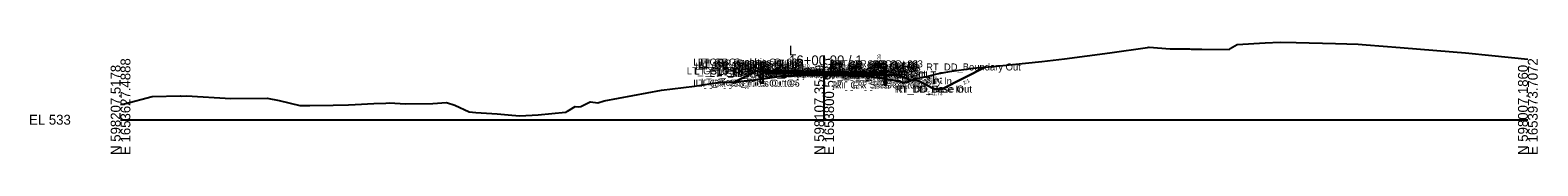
# Model space of a CAD drawing. Extents: x -26 to 403, y -10 to 6021.
# Drawn here: x -25.7 to 402.8, y 4490.3 to 4522.1 of the extents above; entities that cross this region are included whole.
import ezdxf

# ---------------------------------------------------------------- set-up
doc = ezdxf.new("R2010")
doc.units = 0
for name, color, linetype in [('Default', 7, 'Continuous'), ('Exist Cross Section Cell', 7, 'Continuous'), ('Exist XS Ground Line', 7, 'Continuous'), ('Prop CMT Conc Surface', 7, 'Continuous'), ('Prop CMT Concrete Structures', 7, 'Continuous'), ('Prop CMT Ditch DDE', 7, 'Continuous'), ('Prop CMT Guardrail Graphics', 7, 'Continuous'), ('Prop CMT Guardrail SBG', 7, 'Continuous'), ('Prop CMT Pvmt Course 1', 7, 'Continuous'), ('Prop CMT Pvmt Course 2', 7, 'Continuous'), ('Prop CMT Pvmt Course 3', 7, 'Continuous'), ('Prop CMT Pvmt Course SBG', 7, 'Continuous'), ('Prop CMT Pvmt Surface', 7, 'Continuous'), ('Prop CMT Pvmt Surface Shoulder', 7, 'Continuous'), ('Prop CMT Shld Paved Course 1', 7, 'Continuous'), ('Prop CMT Shld Paved Course 2', 7, 'Continuous'), ('Prop CMT Shld Paved Course 3', 7, 'Continuous'), ('Prop CMT Slope Grass', 7, 'Continuous'), ('Prop CMT Subgrade Earthwork', 7, 'Continuous'), ('Prop XS Ditch Slope Text', 7, 'Continuous'), ('Prop XS Ditch Standard Text', 7, 'Continuous'), ('Prop XS Earthwork Shape', 7, 'Continuous'), ('Prop XS Hydro Elevations', 7, 'Continuous'), ('Prop XS SE Text', 7, 'Continuous'), ('Prop XS Side Slope Text', 7, 'Continuous')]:
    doc.layers.add(name, color=color, linetype=linetype)

msp = doc.modelspace()

# ---------------------------------------------------------------- linework, layer by layer
at = {"layer": 'Exist Cross Section Cell'}
for p, q in [((200, 4500), (200, 4518.29)), ((0, 4500), (200, 4500)), ((200, 4500), (400, 4500))]:
    msp.add_line(p, q, dxfattribs=at)
at = {"layer": 'Exist XS Ground Line'}
msp.add_lwpolyline([(0, 4504.47), (1.1, 4504.47), (1.14, 4504.49), (8.98, 4506.58), (17.02, 4506.83), (17.45, 4506.69), (18.72, 4506.8), (31.36, 4506), (41.72, 4506.1), (45.04, 4505.46), (51, 4504.08), (52.98, 4504.02), (53.82, 4504.08), (60.4, 4504.18), (64.75, 4504.27), (66.64, 4504.35), (71.98, 4504.58), (75.42, 4504.73), (76.51, 4504.81), (80.85, 4504.51), (88.73, 4504.62), (92.69, 4504.94), (95.02, 4504.15), (99.13, 4502.25), (101.02, 4502.08), (107.07, 4501.64), (111.26, 4501.34), (113.49, 4501.1), (118.67, 4501.38), (126.43, 4502.17), (126.68, 4502.19), (127.05, 4502.43), (129.22, 4503.79), (130.08, 4503.69), (130.85, 4503.8), (133.14, 4504.95), (133.5, 4505.11), (133.55, 4505.12), (135.69, 4504.83), (137.48, 4505.4), (153.76, 4508.44), (163.12, 4509.52), (170.36, 4510.67), (174.48, 4510.7), (179.92, 4511.23), (187.84, 4512.43), (194.8, 4512.56), (199.74, 4512.67), (200, 4512.66), (209.87, 4512.51), (211.57, 4512.48), (213.96, 4512.08), (220.01, 4511.12), (221.77, 4510.76), (222.74, 4510.5), (223.04, 4510.58), (223.94, 4510.79), (225.2, 4511.36), (225.55, 4511.55), (226.64, 4511.82), (228.27, 4512.07), (229.14, 4512.3), (231.64, 4512.98), (235.64, 4513.72), (242.35, 4514.7), (249.87, 4515.35), (261.9, 4516.52), (268.33, 4517.32), (281.23, 4519.06), (291.85, 4520.55), (292.28, 4520.61), (292.35, 4520.6), (298.31, 4520.12), (303.85, 4520.11), (304.34, 4520.1), (307.32, 4520.07), (315.13, 4519.98), (315.43, 4520.23), (317.39, 4521.36), (325.38, 4521.82), (329.59, 4522.06), (334.12, 4521.98), (345.34, 4521.66), (351.76, 4521.49), (354.05, 4521.33), (363.7, 4520.53), (378.73, 4519.29), (382.28, 4518.98), (389.75, 4518.28), (400, 4517.19)], dxfattribs=at)
at = {"layer": 'Prop CMT Conc Surface'}
msp.add_lwpolyline([(213.81, 4513.48), (216.15, 4513.39), (216.81, 4513.73)], dxfattribs=at)
at = {"layer": 'Prop CMT Concrete Structures'}
for points in [[(213.81, 4513.48), (216.15, 4513.39), (216.81, 4513.73)], [(213.81, 4513.06), (213.81, 4513.48)], [(216.81, 4513.06), (213.81, 4513.06)], [(216.81, 4513.73), (216.81, 4513.06)]]:
    msp.add_lwpolyline(points, dxfattribs=at)
at = {"layer": 'Prop CMT Ditch DDE'}
msp.add_lwpolyline([(224.81, 4511.19), (226.81, 4511.02), (231.39, 4508.73), (233.39, 4508.73), (245.96, 4515.01)], dxfattribs=at)
at = {"layer": 'Prop CMT Guardrail Graphics'}
for points in [[(181.9, 4510.39), (181.9, 4516.39)], [(181.9, 4516.39), (183.23, 4516.39), (183.5, 4516.1)], [(183.5, 4515.52), (183.23, 4515.22), (182.57, 4515.22)], [(182.57, 4515.22), (182.57, 4510.39)], [(183.5, 4516.1), (183.23, 4515.81)], [(183.23, 4515.81), (183.5, 4515.52)], [(182.57, 4510.39), (181.9, 4510.39)]]:
    msp.add_lwpolyline(points, dxfattribs=at)
at = {"layer": 'Prop CMT Guardrail SBG'}
for points in [[(217.75, 4515.89), (216.42, 4515.89), (216.15, 4515.59)], [(216.15, 4515.59), (216.42, 4515.3)], [(216.42, 4515.3), (216.15, 4515.01)], [(216.15, 4515.01), (216.42, 4514.72), (217.08, 4514.72)], [(217.08, 4514.72), (217.08, 4509.89)], [(217.75, 4509.89), (217.75, 4515.89)], [(217.08, 4509.89), (217.75, 4509.89)]]:
    msp.add_lwpolyline(points, dxfattribs=at)
at = {"layer": 'Prop CMT Pvmt Course 1'}
for points in [[(200, 4513.76), (188, 4513.88)], [(188, 4513.88), (188, 4513.67)], [(188, 4513.67), (200, 4513.55)], [(200, 4513.55), (200, 4513.76)], [(200, 4513.76), (212, 4513.52)], [(200, 4513.55), (200, 4513.76)], [(212, 4513.31), (200, 4513.55)], [(212, 4513.52), (212, 4513.31)]]:
    msp.add_lwpolyline(points, dxfattribs=at)
msp.add_lwpolyline([(200, 4513.55), (200, 4513.55), (200, 4513.55), (200, 4513.55)], close=True, dxfattribs=at)
msp.add_lwpolyline([(200, 4513.55), (200, 4513.55), (200, 4513.55), (200, 4513.55)], close=True, dxfattribs=at)
at = {"layer": 'Prop CMT Pvmt Course 2'}
for points in [[(200, 4513.55), (188, 4513.67)], [(188, 4513.67), (188, 4513.46)], [(188, 4513.46), (200, 4513.34)], [(200, 4513.34), (200, 4513.55)], [(200, 4513.34), (200, 4513.55)], [(200, 4513.55), (212, 4513.31)], [(212, 4513.1), (200, 4513.34)], [(212, 4513.31), (212, 4513.1)]]:
    msp.add_lwpolyline(points, dxfattribs=at)
at = {"layer": 'Prop CMT Pvmt Course 3'}
for points in [[(200, 4513.34), (188, 4513.46)], [(188, 4513.46), (188, 4513.13)], [(188, 4513.13), (200, 4513.01)], [(200, 4513.01), (200, 4513.34)], [(200, 4513.34), (212, 4513.1)], [(200, 4513.01), (200, 4513.34)], [(212, 4512.77), (200, 4513.01)], [(212, 4513.1), (212, 4512.77)]]:
    msp.add_lwpolyline(points, dxfattribs=at)
at = {"layer": 'Prop CMT Pvmt Course SBG'}
for points in [[(213.81, 4513.06), (216.81, 4513.06), (217.31, 4513.06), (217.65, 4512.73)], [(213.81, 4512.73), (213.81, 4513.06)], [(217.65, 4512.73), (213.81, 4512.73)]]:
    msp.add_lwpolyline(points, dxfattribs=at)
at = {"layer": 'Prop CMT Pvmt Surface'}
for points in [[(200, 4513.76), (188, 4513.88)], [(200, 4513.76), (212, 4513.52)]]:
    msp.add_lwpolyline(points, dxfattribs=at)
at = {"layer": 'Prop CMT Pvmt Surface Shoulder'}
for points in [[(188, 4513.88), (184, 4513.92)], [(212, 4513.52), (213.81, 4513.48)]]:
    msp.add_lwpolyline(points, dxfattribs=at)
at = {"layer": 'Prop CMT Shld Paved Course 1'}
for points in [[(188, 4513.88), (184, 4513.92), (183.79, 4513.71)], [(183.79, 4513.71), (188, 4513.67)], [(188, 4513.67), (188, 4513.88)], [(212, 4513.52), (213.81, 4513.48)], [(212, 4513.31), (212, 4513.52)], [(213.81, 4513.27), (212, 4513.31)], [(213.81, 4513.48), (213.81, 4513.27)]]:
    msp.add_lwpolyline(points, dxfattribs=at)
at = {"layer": 'Prop CMT Shld Paved Course 2'}
for points in [[(188, 4513.67), (183.79, 4513.71), (183.59, 4513.5)], [(183.59, 4513.5), (188, 4513.46)], [(188, 4513.46), (188, 4513.67)], [(212, 4513.31), (213.81, 4513.27)], [(212, 4513.1), (212, 4513.31)], [(213.81, 4513.06), (212, 4513.1)], [(213.81, 4513.27), (213.81, 4513.06)]]:
    msp.add_lwpolyline(points, dxfattribs=at)
at = {"layer": 'Prop CMT Shld Paved Course 3'}
for points in [[(183.59, 4513.5), (183.26, 4513.17)], [(183.26, 4513.17), (188, 4513.13)], [(188, 4513.46), (183.59, 4513.5)], [(183.59, 4513.5), (183.59, 4513.5)], [(188, 4513.13), (188, 4513.46)], [(212, 4513.1), (213.81, 4513.06)], [(212, 4512.77), (212, 4513.1)], [(213.81, 4512.73), (212, 4512.77)], [(213.81, 4513.06), (213.81, 4512.73)]]:
    msp.add_lwpolyline(points, dxfattribs=at)
at = {"layer": 'Prop CMT Slope Grass'}
for points in [[(180.5, 4513.74), (174.43, 4510.7)], [(183.5, 4513.89), (180.5, 4513.74)], [(184, 4513.92), (183.5, 4513.89)], [(216.81, 4513.73), (217.58, 4514.13), (224.81, 4511.19)]]:
    msp.add_lwpolyline(points, dxfattribs=at)
at = {"layer": 'Prop CMT Subgrade Earthwork'}
for points in [[(183.26, 4513.17), (182.59, 4513.84)], [(188, 4513.13), (183.26, 4513.17)], [(200, 4513.01), (188, 4513.13)], [(200, 4513.01), (212, 4512.77)], [(212, 4512.77), (213.81, 4512.73)], [(213.81, 4512.73), (213.81, 4512.73)], [(213.81, 4512.73), (217.65, 4512.73), (221.02, 4512.73)]]:
    msp.add_lwpolyline(points, dxfattribs=at)
at = {"layer": 'Prop XS Earthwork Shape'}
for points in [[(212, 4512.77), (213.81, 4512.73), (217.65, 4512.73), (221.02, 4512.73), (224.81, 4511.19), (223.94, 4510.79), (223.04, 4510.58), (222.74, 4510.5), (221.77, 4510.76), (220.01, 4511.12), (213.96, 4512.08), (211.57, 4512.48), (209.87, 4512.51), (200, 4512.66), (199.74, 4512.67), (194.8, 4512.56), (187.84, 4512.43), (179.92, 4511.23), (174.48, 4510.7), (174.43, 4510.7), (180.5, 4513.74), (182.59, 4513.84), (183.26, 4513.17), (188, 4513.13), (200, 4513.01)], [(224.81, 4511.19), (225.2, 4511.36), (225.55, 4511.55), (226.64, 4511.82), (228.27, 4512.07), (229.14, 4512.3), (231.64, 4512.98), (235.64, 4513.72), (242.35, 4514.7), (245.96, 4515.01), (233.39, 4508.73), (231.39, 4508.73), (226.81, 4511.02)]]:
    msp.add_lwpolyline(points, close=True, dxfattribs=at)

# ---------------------------------------------------------------- texts
at = {"layer": 'Default'}
for s, height, p in [('LT_GR_Graphics Out 03', 2, (162.8, 4515.39)), ('LT_GR_Graphics Out 02', 2, (164.13, 4515.39)), ('LT_GR_Graphics Out 09', 2, (164.13, 4514.81)), ('LT_GR_Graphics Out 01', 2, (164.97, 4515.1)), ('RT_GR_SBG Out 02', 2, (201.72, 4514.89)), ('RT_GR_SBG Out 03', 2, (203.06, 4514.89)), ('LT_GS_OS_GR_Face_Graphics', 2, (160.96, 4512.89)), ('LT_Sub_Trench_Out_DLT', 2, (163.15, 4512.84)), ('LT_GR_Graphics Out 06', 2, (163.42, 4514.22)), ('LT_GR_Graphics Out 07', 2, (164.13, 4514.22)), ('LT_GR_Graphics Out 08', 2, (164.4, 4514.52)), ('LT_Sub_Trench_Out', 2, (167.46, 4512.17)), ('LT_PS3_Shelf_Out', 2, (169.57, 4512.5)), ('LT_GS_OS_CTL', 2, (169.87, 4512.74)), ('LT_PS3_OEOP', 2, (173.82, 4512.5)), ('LT_PS2_OEOP', 2, (174.03, 4512.71)), ('LT_PS1_OEOP', 2, (174.8, 4512.92)), ('LT_Sub_OEOT', 2, (178.08, 4512.13)), ('LT_PV2_OEOT', 2, (178.17, 4512.67)), ('LT_PV3_OEOT', 2, (178.17, 4512.46)), ('LT_PV1_OEOT', 2, (178.74, 4512.88)), ('RT_Sub_OEEOP', 2, (189.17, 4512.01)), ('LT_Sub_OEEOP', 2, (189.21, 4512.01)), ('RT_PV2_OEEOP', 2, (189.26, 4512.55)), ('RT_PV3_OEEOP', 2, (189.26, 4512.34)), ('LT_PV2_OEEOP', 2, (189.31, 4512.55)), ('LT_PV3_OEEOP', 2, (189.31, 4512.34)), ('RT_Seek SS Fill O', 2, (189.44, 4512.76)), ('RT_PV1_OEEOP', 2, (189.83, 4512.55)), ('LT_PV1_OEEOP', 2, (189.87, 4512.55)), ('RT_PV2_IEEOP', 2, (189.91, 4512.55)), ('LT_PV2_IEEOP', 2, (189.95, 4512.55)), ('RT_PV1_IEEOP', 2, (190.47, 4512.55)), ('LT_PV1_IEEOP', 2, (190.52, 4512.55)), ('PV2_PGL', 2, (193.91, 4512.55)), ('PV1_PGL', 2, (194.47, 4512.76)), ('RT_Sub_OEOP_SBG', 2, (200.22, 4511.73)), ('RT_SBG_C1 Shelf Out', 2, (201.41, 4512.06)), ('RT_GR_SBG Out 08', 2, (201.45, 4514.01)), ('RT_GR_SBG Out 09', 2, (201.72, 4514.3)), ('RT_GR_SBG Out 07', 2, (201.72, 4513.72)), ('RT_GR_SBG Out 01', 2, (202.02, 4514.59)), ('RT_Sub_OEOT', 2, (202.03, 4511.77)), ('RT_PV2_OEOT', 2, (202.13, 4512.31)), ('RT_PV3_OEOT', 2, (202.13, 4512.1)), ('RT_GR_SBG Out 06', 2, (202.34, 4513.72)), ('RT_PV1_OEOT', 2, (202.69, 4512.52)), ('RT_CG_Bot_IE', 2, (203.68, 4512.06)), ('RT_Sub_OEOP', 2, (203.87, 4511.73)), ('RT_PS2_OEOP', 2, (204, 4512.27)), ('RT_PS3_OEOP', 2, (204, 4512.06)), ('RT_CG_Top_Gut', 2, (204.33, 4512.39)), ('RT_PS1_OEOP', 2, (204.57, 4512.48)), ('RT_Sub_SBG Out', 2, (204.78, 4511.73)), ('RT_CG_Top_BOC', 2, (205.05, 4512.73)), ('RT_CG_Bot_BOC', 2, (205.08, 4512.06)), ('RT_GS_OS_CTL', 2, (206.91, 4513.13)), ('RT_Sub_OSS_DLT', 2, (208.37, 4511.73)), ('RT_DD_Boundary Out', 2, (228.98, 4514.01)), ('LT_GR_Graphics Out 04', 2, (162.8, 4509.39)), ('LT_GR_Graphics Out 05', 2, (163.46, 4509.39)), ('LT_Slope_Fill', 2, (164.95, 4509.7)), ('RT_GR_SBG Out 05', 2, (202.39, 4508.89)), ('RT_GR_SBG Out 04', 2, (203.06, 4508.89)), ('RT_DD_Boundary In', 2, (211.46, 4510.02)), ('RT_SS_Fill_Point', 2, (212.45, 4510.19)), ('RT_Slope_Fill', 2, (215.28, 4510.19)), ('RT_DD_Base In', 2, (220.06, 4507.73)), ('RT_DD_Base Out', 2, (220.43, 4507.73)), ('-', 0.0001, (0, 4500))]:
    msp.add_text(s, height=height, dxfattribs=at).set_placement(p)
at = {"layer": 'Exist Cross Section Cell'}
for s, p in [('L', (190, 4518.29)), ('16+00.00 / 1', (190, 4515.49)), ('EL 533', (-26, 4498.6))]:
    msp.add_text(s, height=2.8, dxfattribs=at).set_placement(p)
for s, p in [('E 1653627.4888', (2.8, 4490)), ('E 1653800.5980', (202.8, 4490)), ('E 1653973.7072', (402.8, 4490)), ('N 598207.5178', (0, 4490)), ('N 598107.3519', (200, 4490)), ('N 598007.1860', (400, 4490))]:
    msp.add_text(s, height=2.8, rotation=90, dxfattribs=at).set_placement(p)
at = {"layer": 'Prop XS Ditch Slope Text'}
for rotation, p in [(333.4349, (227.61, 4508.66)), (26.5651, (239.75, 4509.95))]:
    msp.add_text('2:1', height=1, rotation=rotation, dxfattribs=at).set_placement(p)
at = {"layer": 'Prop XS Ditch Standard Text'}
msp.add_text('541.73', height=1, dxfattribs=at).set_placement((229.39, 4506.98))
at = {"layer": 'Prop XS Hydro Elevations'}
msp.add_text('546.39', height=1, rotation=90, dxfattribs=at).set_placement((216.15, 4514.39))
at = {"layer": 'Prop XS SE Text'}
for s, rotation, p in [('0.010', 359.4271, (192.38, 4514.83)), ('0.020', 358.8542, (204.27, 4514.67))]:
    msp.add_text(s, height=1, rotation=rotation, dxfattribs=at).set_placement(p)
at = {"layer": 'Prop XS Side Slope Text'}
for s, rotation, p in [('2:1', 26.5651, (176.42, 4512.54)), ('2.46:1', 337.8781, (219.83, 4514.02))]:
    msp.add_text(s, height=1, rotation=rotation, dxfattribs=at).set_placement(p)

doc.saveas('drawing.dxf')
